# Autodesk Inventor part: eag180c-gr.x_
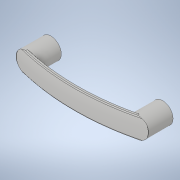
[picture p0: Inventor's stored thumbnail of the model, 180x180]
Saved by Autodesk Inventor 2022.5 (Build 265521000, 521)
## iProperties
Created: 2021-07
Part Number: eag180c-gr.x_
Material: 一般
Document SubType Name: Modeling
Designer: ImaoCorp
Density: 1 g/cm^3
Appearance: 既定
Sending System: SOLIDWORKS 2019-2019304
MC: AMD64
MC_MODEL: Intel64 Family 6 Model 60 Stepping 3, GenuineIntel
OS: Windows_NT
FRU: Parasolid Version 31.0, build 290,  9- 1-2019
FORMAT: text
GUISE: transmit
KEY: eag180c-gr
FILE: eag180c-gr.x_t
DATE: Thu Jul 29 14:21:59 2021
Author: ImaoCorp
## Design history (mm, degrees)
feature "Base1"
node "ソリッド1"
